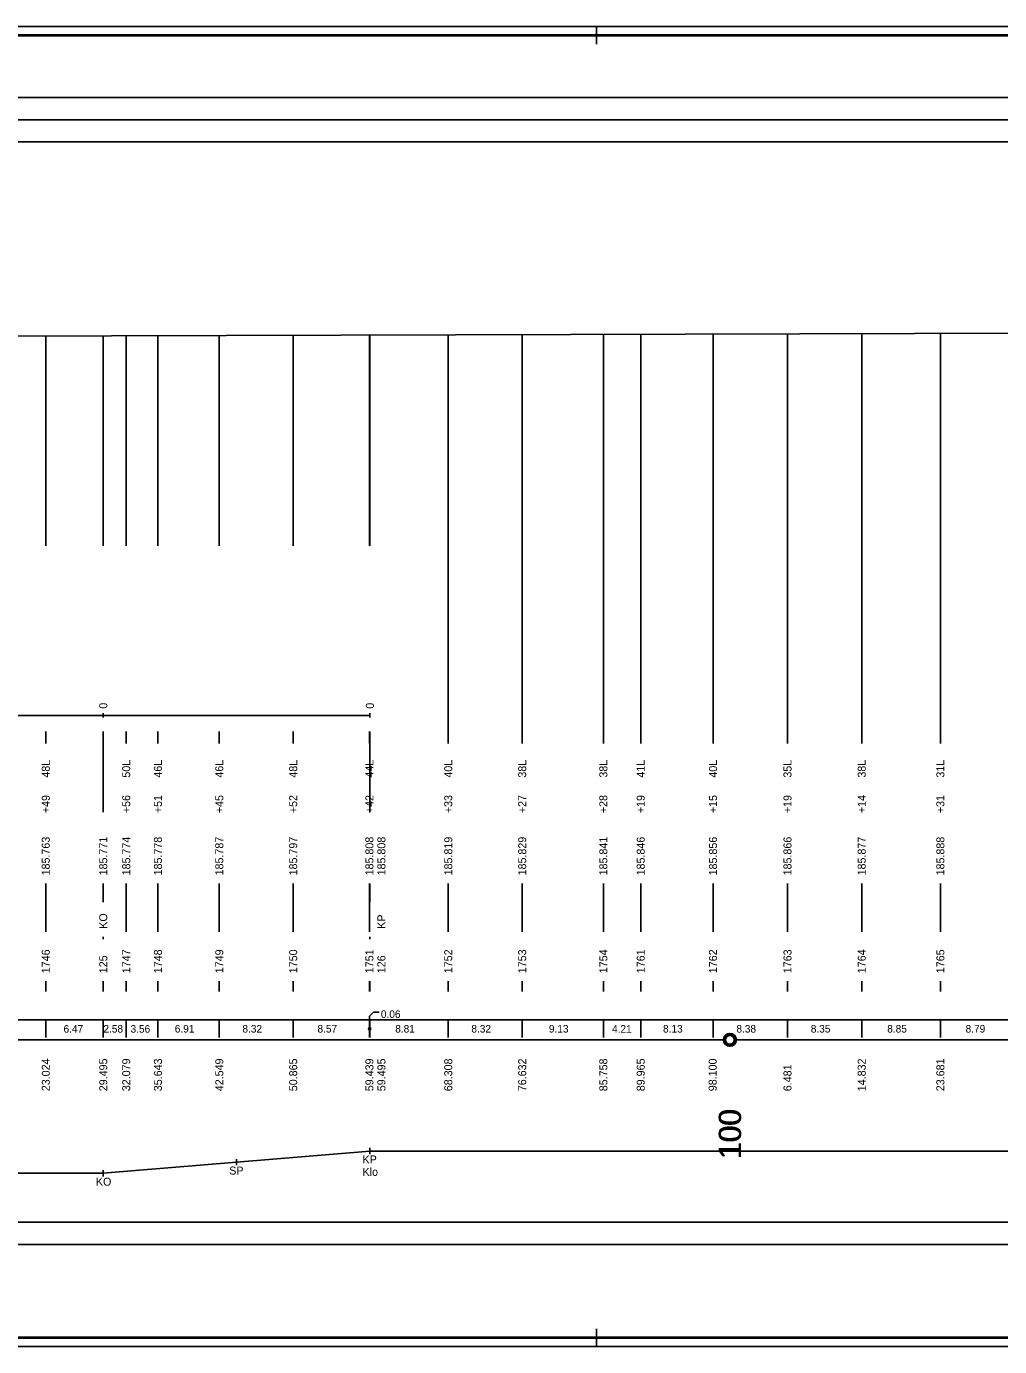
# Model space of a CAD drawing. Extents: x 0 to 10087, y -805 to 297.
# Drawn here: x 7221.7 to 7440.7, y 0 to 297 of the extents above; entities that cross this region are included whole.
import ezdxf

# ---------------------------------------------------------------- set-up
doc = ezdxf.new("R2010")
doc.units = 0
for name, color, linetype in [('CARKY_HODNOT', 7, 'Continuous'), ('KRIV1_CARA', 7, 'Continuous'), ('KRIV1_TEXT', 7, 'Continuous'), ('NIVELETA_CARA', 7, 'Continuous'), ('PREV_CARA', 7, 'Continuous'), ('PREV_TEXT', 7, 'Continuous'), ('RAM', 7, 'Continuous'), ('REZERVA', 7, 'Continuous'), ('STAN_CARA', 7, 'Continuous'), ('STAN_PAS', 7, 'Continuous'), ('STAN_TEXT', 7, 'Continuous'), ('TEXT', 7, 'Continuous'), ('TXT_C_BODU', 7, 'Continuous')]:
    doc.layers.add(name, color=color, linetype=linetype)

msp = doc.modelspace()

# ---------------------------------------------------------------- linework, layer by layer
at = {"layer": 'CARKY_HODNOT'}
for p, q in [((7226.05, 180.14), (7226.05, 227.31)), ((7238.99, 180.14), (7238.99, 227.35)), ((7244.16, 180.14), (7244.16, 227.37)), ((7251.29, 180.14), (7251.29, 227.39)), ((7265.1, 180.14), (7265.1, 227.43)), ((7281.73, 180.14), (7281.73, 227.49)), ((7298.88, 180.14), (7298.88, 227.54)), ((7298.99, 180.14), (7298.99, 227.54)), ((7316.62, 138.35), (7316.62, 227.59)), ((7333.26, 138.35), (7333.26, 227.65)), ((7351.52, 138.35), (7351.52, 227.7)), ((7359.93, 138.35), (7359.93, 227.73)), ((7376.2, 138.35), (7376.2, 227.78)), ((7392.96, 138.35), (7392.96, 227.83)), ((7409.66, 138.35), (7409.66, 227.88)), ((7427.36, 138.35), (7427.36, 227.94)), ((7226.05, 135.65), (7226.05, 138.35)), ((7238.99, 126.2), (7238.99, 138.35)), ((7244.16, 135.65), (7244.16, 138.35)), ((7251.29, 135.65), (7251.29, 138.35)), ((7265.1, 135.65), (7265.1, 138.35)), ((7281.73, 135.65), (7281.73, 138.35)), ((7298.88, 135.65), (7298.88, 138.35)), ((7298.99, 126.2), (7298.99, 138.35)), ((7316.62, 135.65), (7316.62, 138.35)), ((7333.26, 135.65), (7333.26, 138.35)), ((7351.52, 135.65), (7351.52, 138.35)), ((7359.93, 135.65), (7359.93, 138.35)), ((7376.2, 135.65), (7376.2, 138.35)), ((7392.96, 135.65), (7392.96, 138.35)), ((7409.66, 135.65), (7409.66, 138.35)), ((7427.36, 135.65), (7427.36, 138.35)), ((7238.99, 120.25), (7238.99, 126.2)), ((7298.99, 120.25), (7298.99, 126.2)), ((7226.05, 93.3), (7226.05, 104.2)), ((7238.99, 100), (7238.99, 104.2)), ((7244.16, 93.3), (7244.16, 104.2)), ((7251.29, 93.3), (7251.29, 104.2)), ((7265.1, 93.3), (7265.1, 104.2)), ((7281.73, 93.3), (7281.73, 104.2)), ((7298.88, 93.3), (7298.88, 104.2)), ((7298.99, 100), (7298.99, 104.2)), ((7316.62, 93.3), (7316.62, 104.2)), ((7333.26, 93.3), (7333.26, 104.2)), ((7351.52, 93.3), (7351.52, 104.2)), ((7359.93, 93.3), (7359.93, 104.2)), ((7376.2, 93.3), (7376.2, 104.2)), ((7392.96, 93.3), (7392.96, 104.2)), ((7409.66, 93.3), (7409.66, 104.2)), ((7427.36, 93.3), (7427.36, 104.2)), ((7238.99, 91.65), (7238.99, 92.2)), ((7298.99, 91.65), (7298.99, 92.2)), ((7226.05, 79.9), (7226.05, 82.2)), ((7238.99, 79.9), (7238.99, 82.2)), ((7244.16, 79.9), (7244.16, 82.2)), ((7251.29, 79.9), (7251.29, 82.2)), ((7265.1, 79.9), (7265.1, 82.2)), ((7281.73, 79.9), (7281.73, 82.2)), ((7298.88, 79.9), (7298.88, 82.2)), ((7298.99, 79.9), (7298.99, 82.2)), ((7316.62, 79.9), (7316.62, 82.2)), ((7333.26, 79.9), (7333.26, 82.2)), ((7351.52, 79.9), (7351.52, 82.2)), ((7359.93, 79.9), (7359.93, 82.2)), ((7376.2, 79.9), (7376.2, 82.2)), ((7392.96, 79.9), (7392.96, 82.2)), ((7409.66, 79.9), (7409.66, 82.2)), ((7427.36, 79.9), (7427.36, 82.2))]:
    msp.add_line(p, q, dxfattribs=at)
at = {"layer": 'KRIV1_CARA'}
for p, q in [((7298.99, 44), (7298.99, 44.7)), ((7238.99, 39), (7298.99, 44)), ((7268.99, 41.5), (7268.99, 42.2)), ((7298.99, 44), (7298.99, 43.3)), ((7298.99, 44), (7672.87, 44)), ((6645.11, 39), (7238.99, 39)), ((7238.99, 39), (7238.99, 39.7)), ((7238.99, 39), (7238.99, 38.3)), ((7268.99, 41.5), (7268.99, 40.8))]:
    msp.add_line(p, q, dxfattribs=at)
at = {"layer": 'NIVELETA_CARA'}
for p, q in [((300, 281), (8321.33, 281)), ((300, 276), (8321.33, 276)), ((300, 271), (8321.33, 271)), ((7127.38, 227.01), (7522.48, 228.23)), ((500, 28), (8321.33, 28)), ((500, 23), (8321.33, 23))]:
    msp.add_line(p, q, dxfattribs=at)
at = {"layer": 'PREV_CARA'}
for p, q in [((6645.11, 142), (7238.99, 142)), ((7238.99, 142), (7298.99, 142))]:
    msp.add_line(p, q, dxfattribs=at)
at = {"layer": 'PREV_TEXT'}
for p, q in [((7238.99, 141.5), (7238.99, 142.5)), ((7238.99, 141.5), (7238.99, 142.5)), ((7298.99, 141.5), (7298.99, 142.5))]:
    msp.add_line(p, q, dxfattribs=at)
at = {"layer": 'RAM'}
for p, q in [((8636.33, 297), (0, 297)), ((7350, 293), (7350, 297)), ((8634.33, 295.1), (2, 295.1)), ((8634.33, 295), (2, 295)), ((8634.33, 294.9), (2, 294.9)), ((7350, 0), (7350, 4)), ((0, 0), (8636.33, 0)), ((2, 2.1), (8634.33, 2.1)), ((2, 2), (8634.33, 2)), ((2, 1.9), (8634.33, 1.9))]:
    msp.add_line(p, q, dxfattribs=at)
at = {"layer": 'REZERVA'}
for radius in [1.45, 1.4, 1.35, 1.3, 1.25, 1.2, 1.15, 1.1, 1.05, 1]:
    msp.add_circle((7380, 69), radius, dxfattribs=at)
at = {"layer": 'STAN_CARA'}
for p, q in [((7181, 69), (7378.5, 69)), ((7381.5, 69), (7579, 69))]:
    msp.add_line(p, q, dxfattribs=at)
at = {"layer": 'STAN_PAS'}
for p, q in [((7298.93, 74.35), (7299.78, 75.2)), ((7298.93, 71.75), (7298.93, 74.35)), ((7299.78, 75.2), (7301.06, 75.2)), ((300, 73.5), (8321.33, 73.5)), ((7226.05, 69.5), (7226.05, 73.5)), ((7238.99, 69.5), (7238.99, 73.5)), ((7244.16, 69.5), (7244.16, 73.5)), ((7251.29, 69.5), (7251.29, 73.5)), ((7265.1, 69.5), (7265.1, 73.5)), ((7281.73, 69.5), (7281.73, 73.5)), ((7298.88, 69.5), (7298.88, 73.5)), ((7298.99, 69.5), (7298.99, 73.5)), ((7316.62, 69.5), (7316.62, 73.5)), ((7333.26, 69.5), (7333.26, 73.5)), ((7351.52, 69.5), (7351.52, 73.5)), ((7359.93, 69.5), (7359.93, 73.5)), ((7376.2, 69.5), (7376.2, 73.5)), ((7392.96, 69.5), (7392.96, 73.5)), ((7409.66, 69.5), (7409.66, 73.5)), ((7427.36, 69.5), (7427.36, 73.5))]:
    msp.add_line(p, q, dxfattribs=at)
msp.add_circle((7298.93, 71.5), 0.25, dxfattribs=at)

# ---------------------------------------------------------------- texts
at = {"layer": 'KRIV1_TEXT'}
for s, p in [('KP', (7297.34, 41.2)), ('SP', (7267.34, 38.7)), ('Klo', (7297.34, 38.4)), ('KO', (7237.34, 36.2))]:
    msp.add_text(s, height=1.8, dxfattribs=at).set_placement(p)
at = {"layer": 'PREV_TEXT'}
for p in [(7239.89, 143.5), (7299.89, 143.5)]:
    msp.add_text('0', height=1.8, rotation=90, dxfattribs=at).set_placement(p)
at = {"layer": 'STAN_TEXT'}
for s, p in [('0.06', (7301.46, 73.93)), ('6.47', (7230.05, 70.63)), ('2.58', (7239.02, 70.64)), ('3.56', (7245.13, 70.62)), ('6.91', (7255.08, 70.65)), ('8.32', (7270.3, 70.65)), ('8.57', (7287.19, 70.65)), ('8.81', (7304.69, 70.65)), ('8.32', (7321.82, 70.65)), ('9.13', (7339.27, 70.65)), ('4.21', (7353.47, 70.62)), ('8.13', (7364.95, 70.65)), ('8.38', (7381.46, 70.65)), ('8.35', (7398.2, 70.65)), ('8.85', (7415.4, 70.65)), ('8.79', (7433.04, 70.65))]:
    msp.add_text(s, height=1.7, dxfattribs=at).set_placement(p)
for s, height, p in [('23.024', 1.8, (7226.95, 57.45)), ('29.495', 1.8, (7239.89, 57.45)), ('32.079', 1.8, (7245.06, 57.45)), ('35.643', 1.8, (7252.19, 57.45)), ('42.549', 1.8, (7266, 57.45)), ('50.865', 1.8, (7282.63, 57.45)), ('59.439', 1.8, (7299.78, 57.45)), ('59.495', 1.8, (7302.48, 57.45)), ('68.308', 1.8, (7317.52, 57.45)), ('76.632', 1.8, (7334.16, 57.45)), ('85.758', 1.8, (7352.42, 57.45)), ('89.965', 1.8, (7360.83, 57.45)), ('98.100', 1.8, (7377.02, 57.45)), ('6.481', 1.8, (7393.86, 57.45)), ('14.832', 1.8, (7410.56, 57.45)), ('23.681', 1.8, (7428.26, 57.45)), ('   100', 5, (7382.5, 36.8)), ('   100', 5, (7382.5, 36.7)), ('   100', 5, (7382.5, 36.6))]:
    msp.add_text(s, height=height, rotation=90, dxfattribs=at).set_placement(p)
at = {"layer": 'TEXT'}
for s, p in [('48L', (7226.95, 128)), ('50L', (7245.06, 128)), ('46L', (7252.19, 128)), ('46L', (7266, 128)), ('48L', (7282.63, 128)), ('44L', (7299.78, 128)), ('40L', (7317.52, 128)), ('38L', (7334.16, 128)), ('38L', (7352.42, 128)), ('41L', (7360.83, 128)), ('40L', (7377.1, 128)), ('35L', (7393.86, 128)), ('38L', (7410.56, 128)), ('31L', (7428.26, 128)), ('+49', (7226.95, 120)), ('+56', (7245.06, 120)), ('+51', (7252.19, 120)), ('+45', (7266, 120)), ('+52', (7282.63, 120)), ('+42', (7299.78, 120)), ('+33', (7317.52, 120)), ('+27', (7334.16, 120)), ('+28', (7352.42, 120)), ('+19', (7360.83, 120)), ('+15', (7377.1, 120)), ('+19', (7393.86, 120)), ('+14', (7410.56, 120)), ('+31', (7428.26, 120)), ('185.763', (7226.95, 106)), ('185.771', (7239.89, 106)), ('185.774', (7245.06, 106)), ('185.778', (7252.19, 106)), ('185.787', (7266, 106)), ('185.797', (7282.63, 106)), ('185.808', (7299.78, 106)), ('185.808', (7302.48, 106)), ('185.819', (7317.52, 106)), ('185.829', (7334.16, 106)), ('185.841', (7352.42, 106)), ('185.846', (7360.83, 106)), ('185.856', (7377.1, 106)), ('185.866', (7393.86, 106)), ('185.877', (7410.56, 106)), ('185.888', (7428.26, 106)), ('KO', (7239.89, 94)), ('KP', (7302.48, 94))]:
    msp.add_text(s, height=1.8, rotation=90, dxfattribs=at).set_placement(p)
at = {"layer": 'TXT_C_BODU'}
for s, p in [('1746', (7226.95, 84)), ('1747', (7245.06, 84)), ('1748', (7252.19, 84)), ('1749', (7266, 84)), ('1750', (7282.63, 84)), ('1751', (7299.78, 84)), ('1752', (7317.52, 84)), ('1753', (7334.16, 84)), ('1754', (7352.42, 84)), ('1761', (7360.83, 84)), ('1762', (7377.1, 84)), ('1763', (7393.86, 84)), ('1764', (7410.56, 84)), ('1765', (7428.26, 84)), ('125', (7239.89, 84)), ('126', (7302.48, 84))]:
    msp.add_text(s, height=1.8, rotation=90, dxfattribs=at).set_placement(p)

doc.saveas('drawing.dxf')
